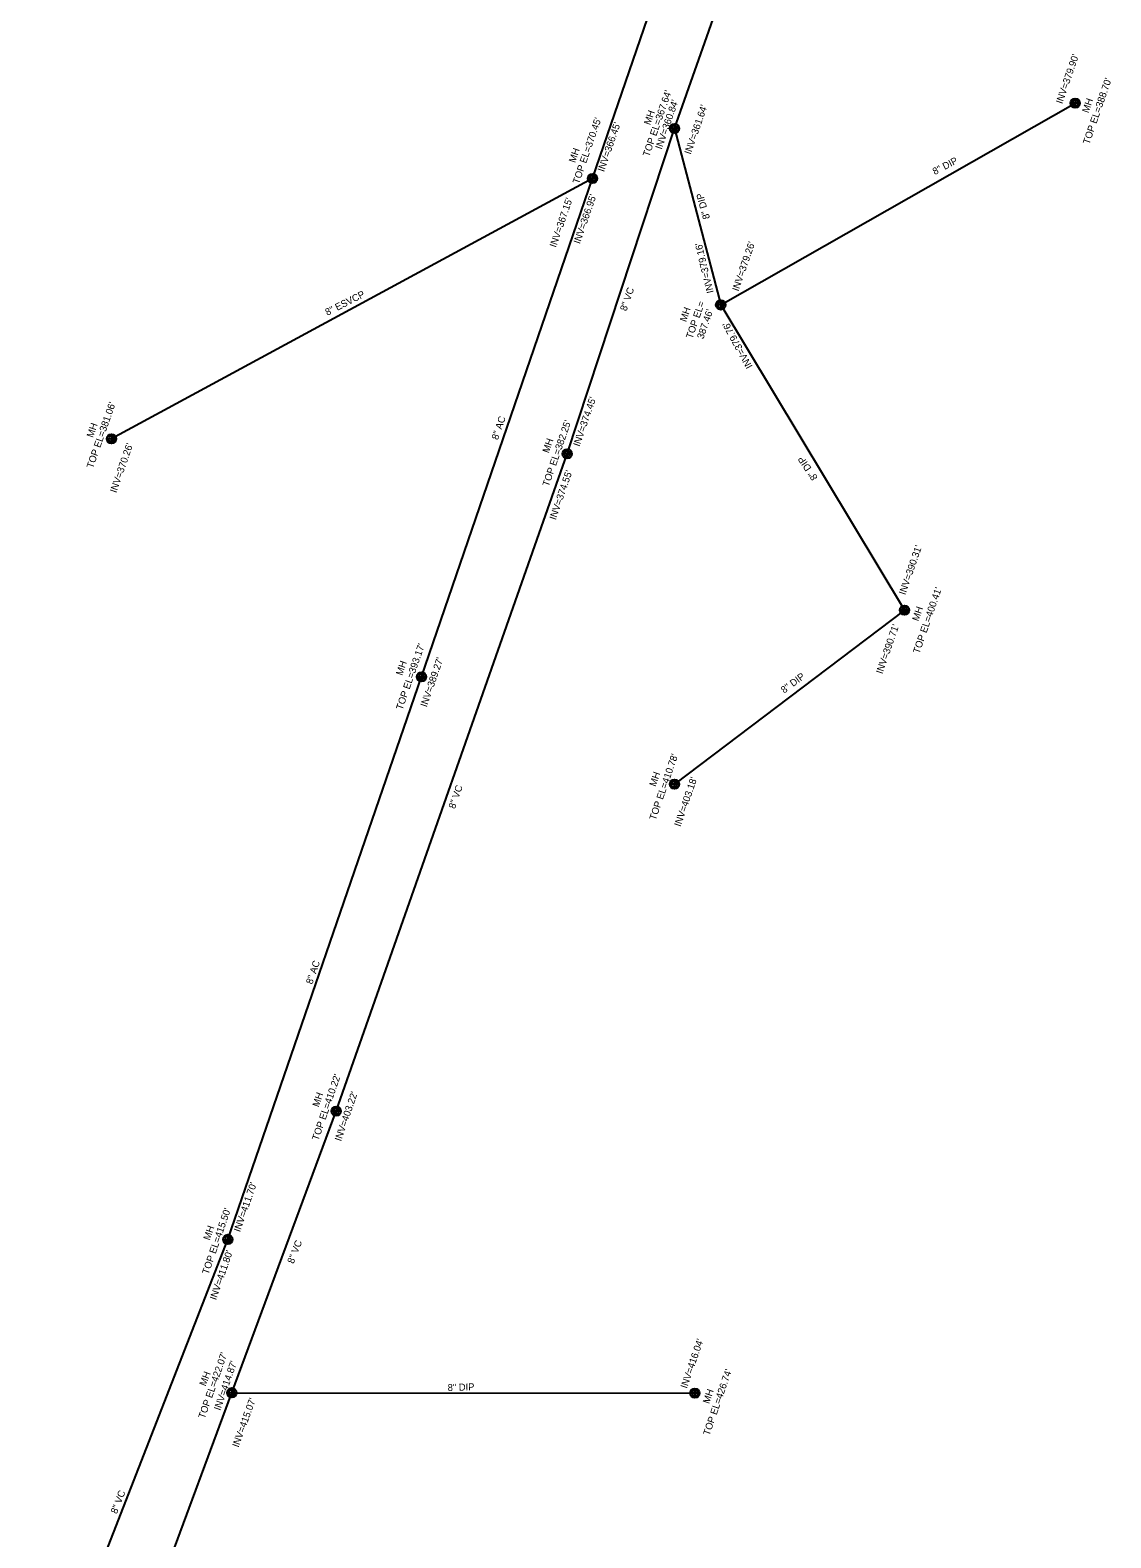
# Model space of a CAD drawing. Extents: x 1975698 to 1978521, y 778259 to 782969.
# Drawn here: x 1977235 to 1977852, y 780640 to 781501 of the extents above; entities that cross this region are included whole.
import ezdxf

# ---------------------------------------------------------------- set-up
doc = ezdxf.new("R2010")
doc.units = 0
for name, color, linetype in [('Old_Level_11', 7, 'Continuous'), ('Prop Horizontal Alignment', 7, 'Continuous'), ('Prop Horizontal Alignment Station Label', 7, 'Continuous'), ('Prop WCC CELL', 7, 'Continuous')]:
    doc.layers.add(name, color=color, linetype=linetype)

# ---------------------------------------------------------------- blocks, each defined once
blk = doc.blocks.new('EXIST UTILITIES SANITARY SEWER MANHOLE')
at = {"layer": 'Prop Horizontal Alignment'}
blk.add_lwpolyline([(0, 0.034), (0, -0.034), (0, 0), (0.034, 0), (-0.034, 0)], dxfattribs=at)
for radius in [0.0539, 0.0342]:
    blk.add_circle((0, 0), radius, dxfattribs=at)

msp = doc.modelspace()

# ---------------------------------------------------------------- linework, layer by layer
at = {"layer": 'Prop Horizontal Alignment Station Label'}
for p, q in [((1977555.78, 781416.47), (1977649.96, 781690.99)), ((1977602.55, 781445), (1977679.17, 781662.62)), ((1977628.93, 781344.28), (1977831.35, 781459.47)), ((1977541.29, 781259.24), (1977602.55, 781445)), ((1977602.55, 781445), (1977628.93, 781344.28)), ((1977555.78, 781416.47), (1977281.08, 781267.85)), ((1977458.12, 781131.96), (1977555.78, 781416.47)), ((1977628.93, 781344.28), (1977733.84, 781170.02)), ((1977409.42, 780883.8), (1977541.29, 781259.24)), ((1977733.84, 781170.02), (1977602.48, 781070.58)), ((1977347.49, 780810.62), (1977458.12, 781131.96)), ((1977349.76, 780723.04), (1977409.42, 780883.8)), ((1977234.68, 780520.98), (1977347.49, 780810.62)), ((1977278.19, 780528.95), (1977349.76, 780723.04)), ((1977349.76, 780723.04), (1977614.2, 780722.73))]:
    msp.add_line(p, q, dxfattribs=at)

# ---------------------------------------------------------------- block references
at = {"layer": 'Prop Horizontal Alignment', "xscale": 50, "yscale": 50}
for p in [(1977831.35, 781459.47), (1977602.55, 781445), (1977555.78, 781416.47), (1977628.93, 781344.28), (1977281.08, 781267.85), (1977541.29, 781259.24), (1977733.84, 781170.02), (1977458.12, 781131.96), (1977602.48, 781070.58), (1977409.42, 780883.8), (1977347.49, 780810.62), (1977349.76, 780723.04), (1977614.2, 780722.73)]:
    msp.add_blockref('EXIST UTILITIES SANITARY SEWER MANHOLE', p, dxfattribs=at)

# ---------------------------------------------------------------- texts
at = {"layer": 'Old_Level_11'}
for s, rotation, p in [('8" DIP', 27.35829, (1977751.14, 781418.44)), ('8" DIP', 105.68474, (1977622.85, 781393.86)), ('8" ESVCP', 26.90923, (1977404.36, 781338.06)), ('8" VC', 71.00236, (1977575.1, 781340.48)), ('8" AC', 71.00236, (1977501.73, 781266.92)), ('8" DIP', 123.94839, (1977684.49, 781245.76)), ('8" DIP', 36.47483, (1977665.1, 781122.26)), ('8" VC', 71.00236, (1977477.18, 781056.2)), ('8" AC', 71.00236, (1977395.75, 780956.02)), ('8" VC', 68.71904, (1977385.05, 780796.4)), ('8" DIP', 1.63546, (1977473.1, 780723.99)), ('8" VC', 68.71904, (1977284.17, 780653.52))]:
    msp.add_text(s, height=4, rotation=rotation, dxfattribs=at).set_placement(p)
at = {"layer": 'Prop WCC CELL'}
for s, rotation, p in [("INV=379.90'", 71.01683, (1977823.92, 781458.85)), ("TOP EL=388.70'", 71.01683, (1977839.35, 781435.71)), ("TOP EL=367.64'", 71.01683, (1977588.06, 781428.64)), ('MH', 71.01683, (1977588.7, 781446.75)), ("INV=360.84'", 71.01683, (1977595.25, 781432.84)), ("INV=361.64'", 71.01683, (1977611.83, 781429.96)), ('MH', 71.01683, (1977838.89, 781453.63)), ("TOP EL=370.45'", 71.01683, (1977548.01, 781413.09)), ("INV=366.45'", 71.01683, (1977562.29, 781420)), ('MH', 71.01683, (1977545.83, 781425.2)), ("INV=367.15'", 71.01683, (1977534.88, 781376.83)), ("INV=366.95'", 71.01683, (1977548.5, 781378.86)), ("INV=379.16'", 103.58291, (1977624.91, 781351.48)), ("INV=379.26'", 71.01683, (1977639.08, 781351.81)), ('TOP EL=', 71.01683, (1977612.72, 781324.67)), ('MH', 71.01683, (1977609.18, 781334.31)), ("387.46'", 71.01683, (1977619.01, 781324.51)), ("INV=379.76'", 118.53707, (1977647.26, 781309.22)), ("INV=374.45'", 71.01683, (1977548.33, 781263.14)), ("TOP EL=381.06'", 70.75421, (1977270.53, 781250.66)), ('MH', 71.0228, (1977270.57, 781268.22)), ("TOP EL=382.25'", 71.01683, (1977530.78, 781240.27)), ('MH', 71.01683, (1977530.77, 781259.4)), ("INV=370.26'", 70.87644, (1977283.86, 781236.67)), ("INV=374.55'", 71.01683, (1977534.74, 781221.22)), ("INV=390.31'", 71.01683, (1977734.3, 781178.38)), ("TOP EL=400.41'", 71.01683, (1977742.33, 781144.82)), ('MH', 71.01683, (1977741.8, 781163.4)), ("INV=390.71'", 71.01683, (1977721.24, 781133.25)), ("TOP EL=393.17'", 71.01683, (1977447.19, 781112.67)), ('MH', 71.01683, (1977447.1, 781132.38)), ("INV=389.27'", 71.01683, (1977461.09, 781114.32)), ("TOP EL=410.78'", 71.01683, (1977591.81, 781049.7)), ('MH', 71.01683, (1977591.78, 781068.95)), ("INV=403.18'", 71.01683, (1977606.02, 781046.03)), ("TOP EL=410.22'", 71.01683, (1977399.21, 780866.76)), ('MH', 71.01683, (1977399.39, 780885.88)), ("INV=403.22'", 71.01683, (1977412.16, 780866.36)), ("INV=411.70'", 71.01683, (1977354.54, 780814.52)), ("TOP EL=415.50'", 71.01683, (1977336.48, 780790.29)), ('MH', 71.01683, (1977337.2, 780809.78)), ("INV=411.80'", 71.01683, (1977340.85, 780775.68)), ("INV=416.04'", 71.01683, (1977609.63, 780725.17)), ("TOP EL=422.07'", 70.70183, (1977334.31, 780707.9)), ("INV=414.87'", 70.73994, (1977343.19, 780712.59)), ('MH', 69.08795, (1977334.84, 780726.47)), ("TOP EL=426.74'", 71.01683, (1977622.51, 780698.28)), ('MH', 71.01683, (1977622.33, 780716.44)), ("INV=415.07'", 69.98144, (1977353.61, 780691.54))]:
    msp.add_text(s, height=4, rotation=rotation, dxfattribs=at).set_placement(p)

doc.saveas('drawing.dxf')
